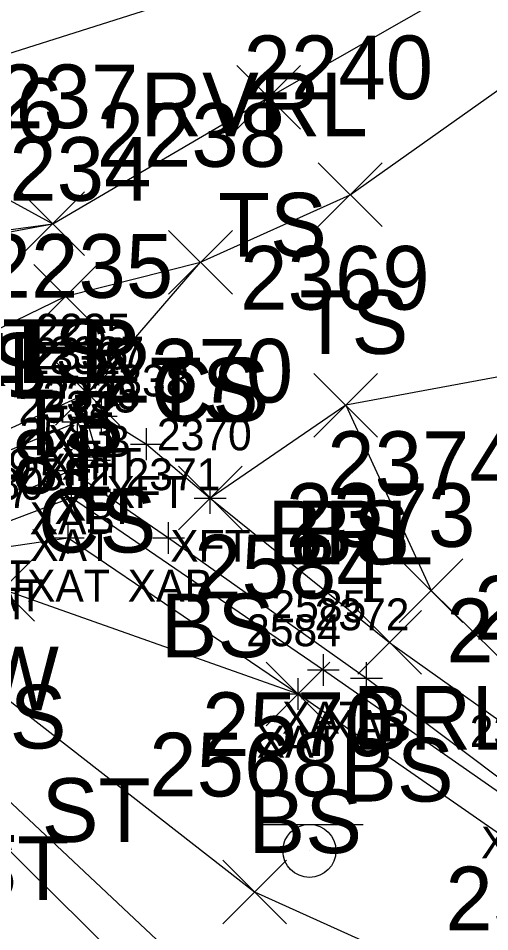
# Model space of a CAD drawing. Extents: x 1504228 to 1506103, y 437717 to 440106.
# Drawn here: x 1505286.34 to 1505301.13, y 438158.68 to 438187.37 of the extents above; entities that cross this region are included whole.
import ezdxf

# ---------------------------------------------------------------- set-up
doc = ezdxf.new("R2010")
doc.units = 0
for name, color, linetype in [('B_A', 7, 'Continuous'), ('B_I', 7, 'Continuous'), ('B_TIC', 7, 'Continuous'), ('BFT', 7, 'Continuous'), ('BSUBM', 7, 'Continuous'), ('L_A', 7, 'Continuous'), ('L_I', 7, 'Continuous'), ('L_TIC', 7, 'Continuous'), ('LABL', 7, 'Continuous'), ('LARO', 7, 'Continuous'), ('LAWE', 7, 'Continuous'), ('LELB', 7, 'Continuous'), ('R_A', 7, 'Continuous'), ('RGR', 7, 'Continuous'), ('RSW', 7, 'Continuous'), ('S_I', 7, 'Continuous'), ('SSGN', 7, 'Continuous'), ('U_A', 7, 'Continuous')]:
    doc.layers.add(name, color=color, linetype=linetype)

msp = doc.modelspace()

# ---------------------------------------------------------------- linework, layer by layer
at = {"layer": 'B_TIC'}
for p, q in [((1505288.514, 438175.592), (1505288.59, 438175.592)), ((1505288.948, 438174.875), (1505289.024, 438174.875)), ((1505288.204, 438174.699), (1505288.28, 438174.699)), ((1505288.477, 438174.841), (1505288.552, 438174.841)), ((1505290.368, 438173.995), (1505290.444, 438173.995)), ((1505288.734, 438173.49), (1505288.809, 438173.49)), ((1505288.839, 438173.592), (1505288.915, 438173.592)), ((1505287.978, 438173.167), (1505288.053, 438173.167)), ((1505288.01, 438172.324), (1505288.085, 438172.324)), ((1505292.366, 438172.302), (1505292.441, 438172.302)), ((1505287.911, 438171.049), (1505287.987, 438171.049)), ((1505291.055, 438171.05), (1505291.131, 438171.05)), ((1505295.917, 438166.903), (1505295.992, 438166.903)), ((1505297.272, 438166.649), (1505297.347, 438166.649)), ((1505295.12, 438166.148), (1505295.196, 438166.148))]:
    msp.add_line(p, q, dxfattribs=at)
for points in [[(1505288.511, 438175.092), (1505288.511, 438176.092)], [(1505288.011, 438175.592), (1505289.011, 438175.592)], [(1505288.201, 438174.199), (1505288.201, 438175.199)], [(1505288.473, 438174.341), (1505288.473, 438175.341)], [(1505288.945, 438174.375), (1505288.945, 438175.375)], [(1505288.445, 438174.875), (1505289.445, 438174.875)], [(1505287.701, 438174.699), (1505288.701, 438174.699)], [(1505287.973, 438174.841), (1505288.973, 438174.841)], [(1505290.365, 438173.495), (1505290.365, 438174.495)], [(1505288.836, 438173.092), (1505288.836, 438174.092)], [(1505289.865, 438173.995), (1505290.865, 438173.995)], [(1505288.73, 438172.99), (1505288.73, 438173.99)], [(1505287.974, 438172.667), (1505287.974, 438173.667)], [(1505288.23, 438173.49), (1505289.23, 438173.49)], [(1505288.336, 438173.592), (1505289.336, 438173.592)], [(1505287.474, 438173.167), (1505288.474, 438173.167)], [(1505288.006, 438171.824), (1505288.006, 438172.824)], [(1505292.362, 438171.802), (1505292.362, 438172.802)], [(1505287.506, 438172.324), (1505288.506, 438172.324)], [(1505291.862, 438172.302), (1505292.862, 438172.302)], [(1505287.908, 438170.549), (1505287.908, 438171.549)], [(1505291.052, 438170.55), (1505291.052, 438171.55)], [(1505287.408, 438171.049), (1505288.408, 438171.049)], [(1505290.552, 438171.05), (1505291.552, 438171.05)], [(1505295.913, 438166.403), (1505295.913, 438167.403)], [(1505297.268, 438166.149), (1505297.268, 438167.149)], [(1505295.413, 438166.903), (1505296.413, 438166.903)], [(1505295.117, 438165.648), (1505295.117, 438166.648)], [(1505296.768, 438166.649), (1505297.768, 438166.649)], [(1505294.617, 438166.148), (1505295.617, 438166.148)]]:
    msp.add_lwpolyline(points, dxfattribs=at)
at = {"layer": 'BFT'}
for points in [[(1505281.289, 438172.305), (1505288.511, 438175.592)], [(1505288.836, 438173.592), (1505288.473, 438174.841), (1505288.945, 438174.875), (1505290.365, 438173.995), (1505292.362, 438172.302)], [(1505211.711, 438138.978), (1505211.593, 438140.8), (1505215.376, 438142.417), (1505230.303, 438149.002), (1505243.278, 438154.766), (1505246.019, 438155.885), (1505263.291, 438163.511), (1505271.064, 438167.183), (1505276.649, 438169.866), (1505288.201, 438174.699), (1505288.73, 438173.49)]]:
    msp.add_lwpolyline(points, dxfattribs=at)
at = {"layer": 'BSUBM'}
for points in [[(1505214.761, 438127.389), (1505213.65, 438134.809), (1505212.657, 438139.975), (1505231.134, 438147.944), (1505243.637, 438153.412), (1505246.753, 438154.837), (1505263.932, 438162.477), (1505271.425, 438165.886), (1505277.465, 438168.561), (1505287.974, 438173.167), (1505291.052, 438171.05), (1505297.268, 438166.649), (1505302.136, 438162.984), (1505307.468, 438159.403), (1505307.306, 438158.962)], [(1505282.757, 438168.549), (1505282.349, 438168.267), (1505281.249, 438169.437), (1505281.958, 438169.702), (1505282.224, 438169.899), (1505283.084, 438168.636), (1505285.392, 438170.489), (1505285.041, 438171.11), (1505285.421, 438171.342), (1505288.006, 438172.324), (1505295.913, 438166.903), (1505307.306, 438158.962)], [(1505285.421, 438171.342), (1505285.832, 438170.749), (1505287.908, 438171.049), (1505295.117, 438166.148)]]:
    msp.add_lwpolyline(points, dxfattribs=at)
at = {"layer": 'L_TIC'}
for points in [[(1505293.194, 438183.889), (1505295.194, 438185.889)], [(1505295.194, 438183.889), (1505293.194, 438185.889)], [(1505295.753, 438180.832), (1505297.753, 438182.832)], [(1505297.753, 438180.832), (1505295.753, 438182.832)], [(1505286.419, 438179.921), (1505288.419, 438181.921)], [(1505288.419, 438179.921), (1505286.419, 438181.921)], [(1505286.419, 438179.921), (1505288.419, 438181.921)], [(1505288.419, 438179.921), (1505286.419, 438181.921)], [(1505286.419, 438179.921), (1505288.419, 438181.921)], [(1505288.419, 438179.921), (1505286.419, 438181.921)], [(1505291.056, 438178.708), (1505293.056, 438180.708)], [(1505293.056, 438178.708), (1505291.056, 438180.708)], [(1505291.056, 438178.708), (1505293.056, 438180.708)], [(1505293.056, 438178.708), (1505291.056, 438180.708)], [(1505286.828, 438177.641), (1505288.828, 438179.641)], [(1505288.828, 438177.641), (1505286.828, 438179.641)], [(1505287.511, 438174.592), (1505289.511, 438176.592)], [(1505289.511, 438174.592), (1505287.511, 438176.592)], [(1505295.615, 438174.22), (1505297.615, 438176.22)], [(1505297.615, 438174.22), (1505295.615, 438176.22)], [(1505295.615, 438174.22), (1505297.615, 438176.22)], [(1505297.615, 438174.22), (1505295.615, 438176.22)], [(1505291.362, 438171.302), (1505293.362, 438173.302)], [(1505293.362, 438171.302), (1505291.362, 438173.302)], [(1505284.843, 438168.435), (1505286.843, 438170.435)], [(1505286.843, 438168.435), (1505284.843, 438170.435)], [(1505298.292, 438168.398), (1505300.292, 438170.398)], [(1505300.292, 438168.398), (1505298.292, 438170.398)], [(1505296.993, 438166.769), (1505298.993, 438168.769)], [(1505298.993, 438166.769), (1505296.993, 438168.769)], [(1505294.117, 438165.148), (1505296.117, 438167.148)], [(1505296.117, 438165.148), (1505294.117, 438167.148)], [(1505292.755, 438158.929), (1505294.755, 438160.929)], [(1505294.755, 438158.929), (1505292.755, 438160.929)]]:
    msp.add_lwpolyline(points, dxfattribs=at)
at = {"layer": 'LABL'}
msp.add_lwpolyline([(1505412.94, 438279.434), (1505408.751, 438263.902), (1505393.358, 438239.3), (1505379.992, 438219.583), (1505364.652, 438204.996), (1505342.27, 438194.948), (1505325.182, 438184.758), (1505314.631, 438179.74), (1505312.566, 438178.307), (1505308.953, 438177.263), (1505304.583, 438176.7), (1505296.615, 438175.22), (1505299.292, 438169.398), (1505303.904, 438164.856), (1505308.252, 438160.874), (1505313.047, 438161.473), (1505317.495, 438164.603), (1505327.49, 438169.4), (1505342.058, 438174.403)], dxfattribs=at)
at = {"layer": 'LARO'}
for points in [[(1505280.716, 438184.584), (1505287.419, 438180.921)], [(1505225.066, 438161.326), (1505226.248, 438169.057), (1505228.34, 438173.672), (1505225.288, 438173.876), (1505239.482, 438178.474), (1505243.528, 438176.585), (1505251.729, 438176.792), (1505258.116, 438181.066), (1505273.159, 438181.503), (1505274.516, 438179.171), (1505287.419, 438180.921)], [(1505211.067, 438140.867), (1505215.631, 438142.954), (1505229.653, 438148.999), (1505242.992, 438154.978), (1505245.889, 438156.33), (1505263.257, 438163.856), (1505270.634, 438167.43), (1505277.265, 438170.598), (1505281.289, 438172.305), (1505281.518, 438175.58), (1505285.106, 438180.489), (1505287.419, 438180.921)]]:
    msp.add_lwpolyline(points, dxfattribs=at)
at = {"layer": 'LAWE'}
msp.add_lwpolyline([(1505191.715, 438146.002), (1505202.906, 438148.803), (1505214.791, 438151.569), (1505218.42, 438155.881), (1505225.066, 438161.326), (1505233.297, 438167.151), (1505239.085, 438170.522), (1505246.461, 438173.024), (1505251.729, 438176.792), (1505260.319, 438178.7), (1505267.708, 438179.756), (1505273.159, 438181.503), (1505280.716, 438184.584), (1505293.606, 438188.67), (1505306.287, 438194.997), (1505316.183, 438195.439), (1505329.815, 438205.572), (1505347.823, 438213.433)], dxfattribs=at)
at = {"layer": 'LELB'}
for points in [[(1505287.419, 438180.921), (1505294.194, 438184.889), (1505305.914, 438191.586), (1505317.977, 438192.973), (1505331.239, 438203.009), (1505347.587, 438211.637), (1505370.579, 438230.634), (1505379.879, 438246.354), (1505394.187, 438272.178), (1505403.001, 438285.772)], [(1505283.082, 438168.26), (1505293.755, 438159.929), (1505303.056, 438155.723), (1505307.447, 438154.511), (1505318.234, 438150.525), (1505336.416, 438150.851), (1505352.472, 438164.545), (1505373.298, 438174.049), (1505384.454, 438185.345), (1505390.057, 438193.61)], [(1505280.724, 438166.502), (1505281.778, 438166.802), (1505283.082, 438168.26), (1505285.843, 438169.435), (1505295.117, 438166.148), (1505307.071, 438157.841), (1505319.301, 438158.173), (1505335.681, 438162.149), (1505348.978, 438167.874), (1505368.148, 438177.626), (1505382.147, 438186.406), (1505384.268, 438190.42)], [(1505215.631, 438142.954), (1505216.782, 438152.684), (1505223.21, 438155.651), (1505231.417, 438162.88), (1505240.87, 438166.496), (1505250.977, 438169.557), (1505260.591, 438172.084), (1505271.035, 438170.915), (1505277.265, 438170.598), (1505281.518, 438175.58), (1505287.828, 438178.641), (1505292.056, 438179.708), (1505296.753, 438181.832), (1505306.221, 438188.545)], [(1505288.511, 438175.592), (1505292.056, 438179.708)], [(1505296.615, 438175.22), (1505292.362, 438172.302), (1505297.993, 438167.769), (1505303.084, 438164.144), (1505307.468, 438159.403), (1505308.252, 438160.874)]]:
    msp.add_lwpolyline(points, dxfattribs=at)
at = {"layer": 'RGR'}
msp.add_lwpolyline([(1505281.778, 438166.802), (1505300.096, 438149.564), (1505306.202, 438145.976), (1505313.175, 438145.226)], dxfattribs=at)
at = {"layer": 'RSW'}
msp.add_lwpolyline([(1505277.038, 438164.677), (1505280.724, 438166.502), (1505298.089, 438149.32), (1505295.889, 438147.093)], dxfattribs=at)
at = {"layer": 'SSGN'}
for p, q in [((1505293.826, 438162.052), (1505297.159, 438162.052)), ((1505295.473, 438161.219), (1505295.473, 438161.219))]:
    msp.add_line(p, q, dxfattribs=at)
msp.add_circle((1505295.473, 438161.219), 0.833, dxfattribs=at)

# ---------------------------------------------------------------- texts
at = {"layer": 'B_A'}
for s, p in [('XFB', (1505287.271, 438173.592)), ('XFT', (1505287.217, 438172.841)), ('XFT', (1505287.689, 438172.875)), ('XFT', (1505286.945, 438172.699)), ('XFT', (1505289.109, 438171.995)), ('XFT', (1505287.58, 438171.592)), ('XFT', (1505287.475, 438171.49)), ('XAB', (1505286.695, 438171.167)), ('XAT', (1505286.711, 438170.324)), ('XFT', (1505291.106, 438170.302)), ('XAT', (1505284.126, 438169.342)), ('XAT', (1505284.126, 438169.342)), ('XAT', (1505286.612, 438169.049)), ('XAB', (1505289.772, 438169.05)), ('XAT', (1505284.537, 438168.749)), ('XAT', (1505284.097, 438168.489)), ('XAT', (1505294.618, 438164.903)), ('XAB', (1505295.989, 438164.649)), ('XAT', (1505293.822, 438164.148)), ('XAB', (1505300.857, 438160.984))]:
    msp.add_text(s, height=1, dxfattribs=at).set_placement(p)
at = {"layer": 'B_I'}
for s, p in [('2235', (1505286.881, 438177.092)), ('2332', (1505286.571, 438176.199)), ('2336', (1505286.816, 438176.341)), ('2337', (1505287.315, 438176.375)), ('2338', (1505288.735, 438175.495)), ('2333', (1505287.101, 438174.99)), ('2335', (1505287.206, 438175.092)), ('2334', (1505286.345, 438174.667)), ('2583', (1505286.376, 438173.824)), ('2370', (1505290.689, 438173.802)), ('2579', (1505283.787, 438172.842)), ('2579', (1505283.787, 438172.842)), ('2582', (1505286.278, 438172.549)), ('2371', (1505289.705, 438172.55)), ('2580', (1505284.159, 438172.249)), ('2577', (1505283.762, 438171.989)), ('2585', (1505294.283, 438168.403)), ('2372', (1505295.638, 438168.149)), ('2584', (1505293.487, 438167.648)), ('2377', (1505300.506, 438164.484))]:
    msp.add_text(s, height=1, dxfattribs=at).set_placement(p)
at = {"layer": 'L_A'}
for s, p in [('RVRL', (1505290.173, 438183.67)), ('TS', (1505292.604, 438179.889)), ('TS', (1505295.163, 438176.832)), ('LER', (1505285.002, 438175.921)), ('LEL', (1505285.057, 438175.921)), ('TS', (1505285.829, 438175.921)), ('LEL', (1505282.744, 438175.489)), ('CS', (1505283.547, 438175.489)), ('TS', (1505290.465, 438174.708)), ('CS', (1505290.497, 438174.708)), ('TS', (1505286.237, 438173.641)), ('CS', (1505286.952, 438170.592)), ('BRL', (1505294.159, 438170.22)), ('BS', (1505295.056, 438170.22)), ('BS', (1505290.803, 438167.302)), ('BS', (1505284.284, 438164.435)), ('BRL', (1505296.836, 438164.398)), ('BS', (1505296.434, 438162.769)), ('BS', (1505293.558, 438161.148))]:
    msp.add_text(s, height=2, dxfattribs=at).set_placement(p)
at = {"layer": 'L_I'}
for s, p in [('2240', (1505293.407, 438184.832)), ('2237', (1505284.159, 438183.921)), ('2237', (1505284.159, 438183.921)), ('2237', (1505284.159, 438183.921)), ('2236', (1505281.791, 438183.489)), ('2236', (1505281.791, 438183.489)), ('2238', (1505288.796, 438182.708)), ('2238', (1505288.796, 438182.708)), ('2234', (1505284.568, 438181.641)), ('2235', (1505285.251, 438178.592)), ('2369', (1505293.3, 438178.22)), ('2369', (1505293.3, 438178.22)), ('2370', (1505289.016, 438175.302)), ('2581', (1505283.15, 438172.435)), ('2374', (1505296.032, 438172.398)), ('2373', (1505294.734, 438170.769)), ('2584', (1505291.857, 438169.148)), ('2375', (1505300.644, 438167.856)), ('2376', (1505299.769, 438167.144)), ('2568', (1505290.448, 438162.929)), ('2569', (1505299.741, 438158.723))]:
    msp.add_text(s, height=2, dxfattribs=at).set_placement(p)
at = {"layer": 'R_A'}
for s, p in [('SWP1 BS1 ST', (1505272.952, 438161.502)), ('RDP1 SWP1 ST', (1505268.321, 438159.677))]:
    msp.add_text(s, height=2, dxfattribs=at).set_placement(p)
at = {"layer": 'S_I'}
msp.add_text('2570', height=2, dxfattribs=at).set_placement((1505292.107, 438164.198))
at = {"layer": 'U_A'}
msp.add_text('SUBW', height=2, dxfattribs=at).set_placement((1505279.591, 438165.638))

doc.saveas('drawing.dxf')
